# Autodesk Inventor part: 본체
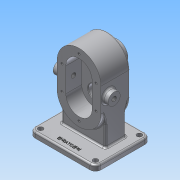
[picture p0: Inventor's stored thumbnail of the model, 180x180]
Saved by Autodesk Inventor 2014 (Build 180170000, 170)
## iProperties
Created: 2020-09
Part Number: 본체
Material: 알루미늄 6061
Document SubType Name: Modeling
Designer: net
Density: 2.71 g/cm^3
Appearance: 알루미늄 - 평지
Mass: 1446.18 g
Surface Area: 785.653 cm^2
Volume: 533.647 cm^3
Author: net
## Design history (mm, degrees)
sketch "스케치1"
  geometry: L1 (-60, -50)-(60, -50); L2 (60, -50)-(60, 50); L3 (60, 50)-(-60, 50); L4 (-60, 50)-(-60, -50); L5 (-60, -50)-(60, 50); L6 (60, -50)-(-60, 50); 1 further point
  constraints: 12 end point, 2 midpoint, 2 parallel, 1 horizontal, 1 perpendicular
  dimensions: "d0" = 120 distance of L2.end L3.end; "d1" = 100 distance of L3.end L1.start
extrude "돌출1" new body sketch "스케치1" distance "d2" = 10; taper "d3" = 0 deg
sketch "스케치3"
  geometry: L1 (60, 50)-(-60, 50) reference; L2 (-40, -12)-(40, -12); L3 (40, -12)-(40, 25); L4 (40, 25)-(-40, 25); L5 (-40, 25)-(-40, -12); L6 (-40, -12)-(40, 25); L7 (40, -12)-(-40, 25); 3 further points
  constraints: 12 end point, 3 midpoint, 2 parallel, 1 horizontal, 1 perpendicular, 1 vertical alignment
  dimensions: "d4" = 80 distance of L3.end L4.end; "d5" = 37 distance of L2.end L3.end; "d6" = 25 distance between parallel lines of L1 L4
extrude "돌출2" join sketch "스케치3" distance "d7" = 80; taper "d8" = 0 deg
sketch "스케치4"
  geometry: L1 (-40, -12)-(40, -12) reference; L2 (40, -12)-(40, 25) reference; L3 (40, 25)-(-40, 25) reference; L4 (-40, 25)-(-40, -12) reference; L5 (-40, 6.5)-(40, 6.5); 1 further point
  constraints: 2 end point, 2 midpoint
sketch "스케치5"
  geometry: L1 (0, 37)-(0, 0) reference; L2 (0, 37)-(-80, 37) reference; L3 (-80, 0)-(-80, 37) reference; L4 (0, 0)-(-80, 0) reference; L5 (-80, 18.5)-(0, 18.5); 1 further point
  constraints: 2 end point, 2 midpoint
node "작업 평면1"
sketch "스케치6"
  geometry: L1 (40, 22)-(40, -22); L2 (80, 22)-(80, -22); L3 (0, -22)-(0, 22); L4 (0, 0)-(80, 0) reference; A1 r 40 centre (40, 22) between (80, 22) and (0, 22); A2 r 40 centre (40, -22) between (0, -22) and (80, -22); 4 further points
  constraints: 8 end point, 4 point on circle, 4 tangent, 3 midpoint, 2 centre point, 2 coincident, 1 parallel, 1 vertical, 1 vertical alignment
  dimensions: "d9" = 22 distance of point (40, 0) L1.end; "d10" = 40 radius of A2
extrude "돌출3" join sketch "스케치6" distance "d11" = 26.5; taper "d13" = 0 deg; dims "d12" = 26.5, "d14" = 0
sketch "스케치7"
  geometry: L1 (80, -22)-(80, 22) reference; L2 (40, -22)-(40, 22); L3 (16, -22)-(16, 22); L4 (64, 22)-(64, -22); A1 r 40 centre (40, 22) between (80, 22) and (0, 22) reference; A2 r 40 centre (40, -22) between (0, -22) and (80, -22) reference; A3 r 24 centre (40, -22) between (16, -22) and (64, -22); A4 r 24 centre (40, 22) between (64, 22) and (16, 22); 2 further points
  constraints: 8 end point, 4 point on circle, 4 tangent, 2 centre point, 2 parallel, 1 coincident, 1 midpoint
  dimensions: "d15" = 24 radius of A4
extrude "돌출4" cut sketch "스케치7" distance "d16" = 29; taper "d17" = 0 deg
sketch "스케치8"
  geometry: C1 r 12.5 at (40, 22); C2 r 12.5 at (40, -22); A1 r 24 centre (40, -22) between (16, -22) and (64, -22) reference; A2 r 24 centre (40, 22) between (64, 22) and (16, 22) reference; 1 further point
  constraints: 2 centre point, 2 coincident
  dimensions: "d18" = 25 diameter of C1; "d19" = 25 diameter of C2
extrude "돌출5" cut sketch "스케치8" distance "d20" = 15; taper "d21" = 0 deg
chamfer "모따기1" distance "d22" = 1; stored, may be unused: second distance "d23" = 2, angle "d24" = 45 deg
fillet "모깎기1" dims "d25" = 10
fillet "모깎기2" dims "d26" = 3
fillet "모깎기3" dims "d27" = 3
fillet "모깎기4" dims "d28" = 3
fillet "모깎기5" dims "d29" = 3
sketch "스케치9"
  geometry: C1 r 19 at (40, -22); A1 r 37 centre (40, -22) between (3, -22) and (77, -22) reference; 1 further point
  constraints: 1 centre point, 1 coincident
  dimensions: "d30" = 38 diameter of C1
extrude "돌출6" join sketch "스케치9" distance "d31" = 17; taper "d32" = 0 deg
fillet "모깎기6" dims "d33" = 3
sketch "스케치10"
  geometry: C1 r 19 at (0, 0) reference; C2 r 14 at (0, 0); 1 further point
  constraints: 1 centre point, 1 coincident
  dimensions: "d34" = 28 diameter of C2
extrude "돌출7" cut sketch "스케치10" distance "d35" = 7.3; taper "d36" = 0 deg
sketch "스케치11"
  geometry: C1 r 12.5 at (0, 0) reference; C2 r 8.5 at (0, 0); 1 further point
  constraints: 1 centre point, 1 coincident
  dimensions: "d37" = 17 diameter of C2
extrude "돌출8" cut sketch "스케치11" stored distance "d38" = 7.3; taper "d39" = 0 deg
sketch "스케치12"
  geometry: L1 (50, 93)-(50, 131) reference; L2 (50, 112)-(0, 112); L3 (50, 126)-(42.7, 126) reference; L4 (50, 126)-(49.3, 126); L5 (49.3, 126)-(50, 126.404); L6 (50, 126)-(50, 126.404); 1 further point
  constraints: 8 end point, 2 point on line, 1 collinear, 1 midpoint, 1 perpendicular
  dimensions: "d40" = 30 deg angle of L4 L5; "d41" = 0.7 distance of L3.start L4.end
revolve "회전1" sketch "스케치12" stored, may be unused: angle "d42" = 90 deg
fillet "모깎기7" dims "d43" = 0.5
sketch "스케치13"
  geometry: L1 (0, 22)-(0, -22) reference; L2 (40, 22)-(40, 53); L3 (40, 22)-(9, 22); L4 (40, 22)-(71, 22); L5 (40, -22)-(9, -22); L6 (40, -22)-(71, -22); L7 (40, -22)-(40, -53); A1 r 40 centre (40, 22) between (80, 22) and (0, 22) reference; A2 r 40 centre (40, -22) between (0, -22) and (80, -22) reference; A3 r 31 centre (40, 22) between (40, 53) and (9, 22); A4 r 31 centre (40, -22) between (9, -22) and (71, -22); 1 further point
  constraints: 12 end point, 6 point on circle, 2 centre point, 2 coincident, 2 collinear, 2 parallel, 2 perpendicular
  dimensions: "d44" = 62 diameter of A3; "d45" = 62 diameter of A4
hole "구멍1" sketch "스케치13" at (40, 53), (9, 22), (71, 22), (9, -22), (71, -22), (40, -53) diameter "d46" = 4.134; stored, may be unused: countersink angle "d50" = 90 deg, drill point angle "d52" = 118 deg; dims "d47" = 10, "d48" = 4, "d49" = 2, "d51" = 12
sketch "스케치14"
  geometry: C1 r 4.5 at (-50, 40); C2 r 4.5 at (-50, -40); C3 r 4.5 at (50, -40); C4 r 4.5 at (50, 40); A1 r 7 centre (50, 40) between (57, 40) and (50, 47) reference; A2 r 7 centre (-50, 40) between (-50, 47) and (-57, 40) reference; A3 r 7 centre (-50, -40) between (-57, -40) and (-50, -47) reference; A4 r 7 centre (50, -40) between (50, -47) and (57, -40) reference; 1 further point
  constraints: 4 centre point, 4 coincident, 3 equal radius
  dimensions: "d53" = 9 diameter of C1
extrude "돌출9" cut sketch "스케치14" stored distance "d54" = 7.3; taper "d55" = 0 deg
sketch "스케치15"
  geometry: L1 (44, 0)-(0, 0) reference; L2 (112, -20)-(112, 60) reference; C1 r 11 at (22, 14); 1 further point
  constraints: 1 centre point
  dimensions: "d56" = 90 distance from line of L2 C1.centre; "d57" = 14 distance from line of L1 C1.centre; "d58" = 22 diameter of C1
extrude "돌출10" join sketch "스케치15" distance "d59" = 10; taper "d60" = 0 deg
fillet "모깎기8" dims "d61" = 3
sketch "스케치16"
  geometry: C1 r 11 at (0, 0) reference; 1 further point
hole "구멍2" sketch "스케치16" at (0, 0) diameter "d62" = 8.376; stored, may be unused: countersink angle "d66" = 90 deg, drill point angle "d68" = 118 deg; dims "d63" = 10, "d64" = 4, "d65" = 2, "d67" = 12
sketch "스케치17"
  geometry: C1 r 11 at (0, 0) reference; 1 further point
hole "구멍3" sketch "스케치17" at (0, 0) diameter "d69" = 8.376; stored, may be unused: countersink angle "d73" = 90 deg, drill point angle "d75" = 118 deg; dims "d70" = 10, "d71" = 4, "d72" = 2, "d74" = 12
sketch "스케치18"
  geometry: L1 (-50, -50)-(50, -50) reference; L2 (-60, 40)-(-60, -40) reference; 2 further points
  constraints: 1 other
  dimensions: "d76" = 12 distance from line of L1 point (0, -38); "d77" = 60 distance from line of L2 point (0, -38)
extrude "돌출11" join sketch "스케치18" distance "d78" = 0.5; taper "d79" = 0 deg
node "솔리드1"
mirror "대칭1"
